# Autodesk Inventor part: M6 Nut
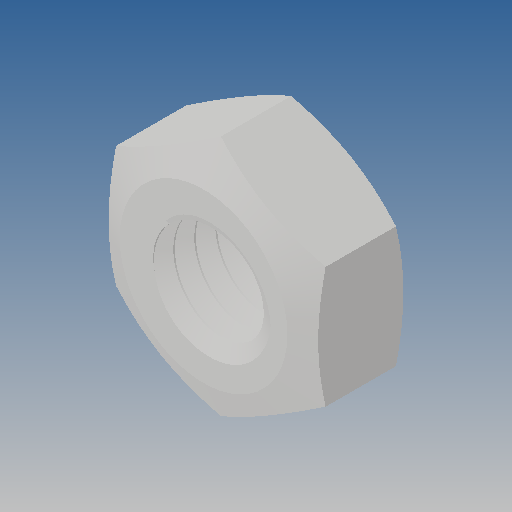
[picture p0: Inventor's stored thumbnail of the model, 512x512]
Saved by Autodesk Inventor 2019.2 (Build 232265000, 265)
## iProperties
Created: 2012-09
Part Number: M6 Nut
Material: Ogólny
Document SubType Name: Modeling
Designer: CADENGINEERING4
Density: 1 g/cm^3
Appearance: Domyślna
Author: CADENGINEERING4
Revision Number: ÈÎºÎ
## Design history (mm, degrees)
feature "ÇÐ³ý-É¨Ãè1"
node "Bryła1"
